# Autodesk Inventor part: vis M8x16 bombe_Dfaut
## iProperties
Created: 2006-03
Part Number: vis M8x16 bombe_Dfaut
Document SubType Name: Modeling
Designer: Flavien MARTY
Author: Flavien MARTY
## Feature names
1. Base1
